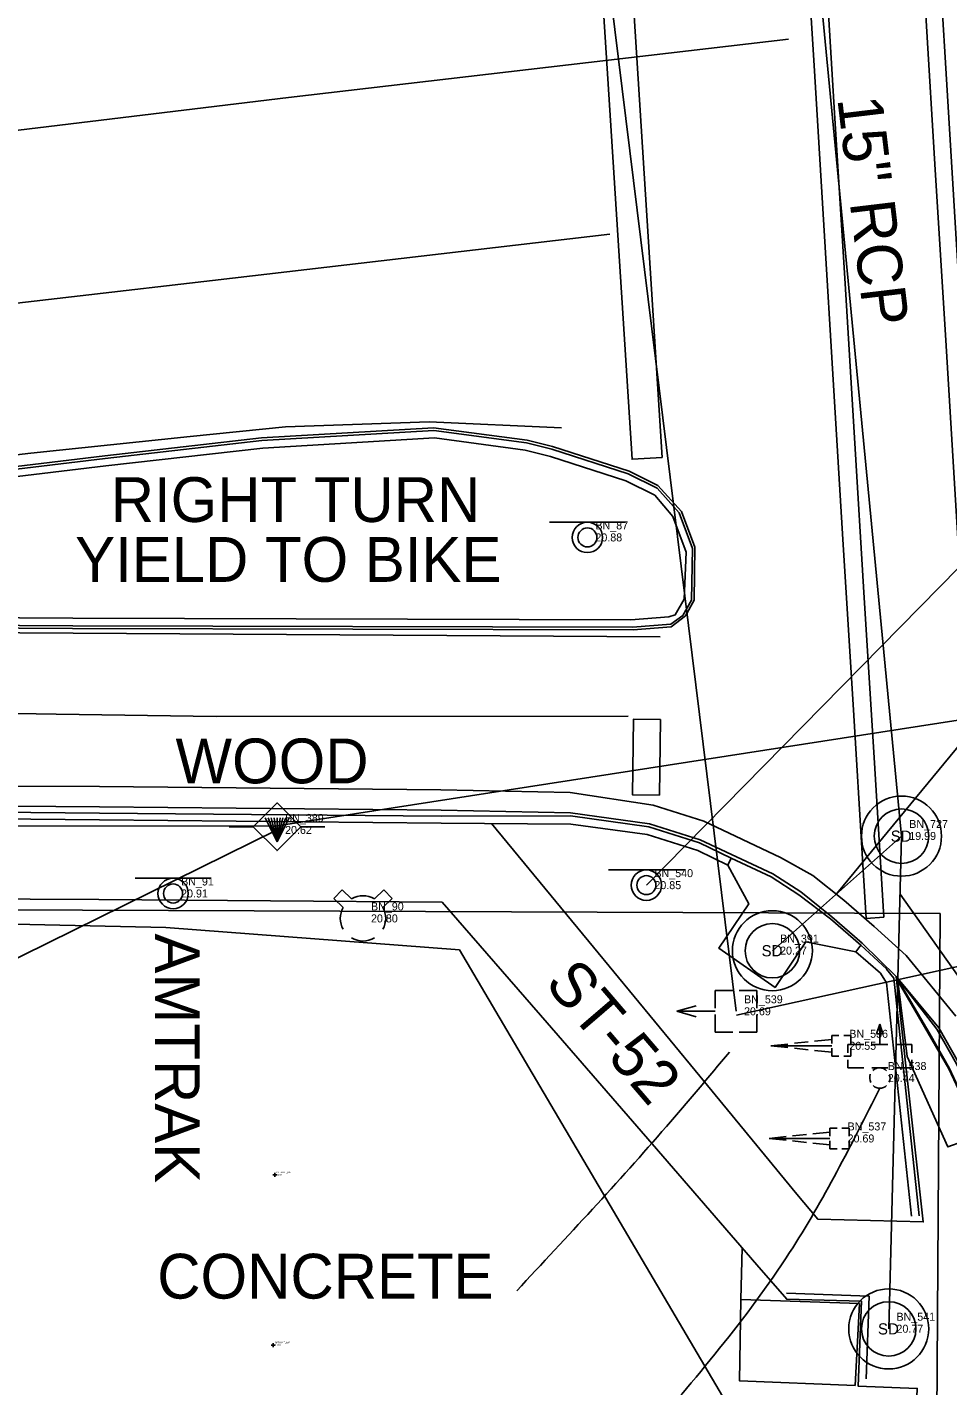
# Model space of a CAD drawing. Extents: x 509744 to 512285, y 1314862 to 1316822.
# Drawn here: x 510403.6 to 510461.1, y 1315900.5 to 1315985.3 of the extents above; entities that cross this region are included whole.
import ezdxf

# ---------------------------------------------------------------- set-up
doc = ezdxf.new("R2010")
doc.units = 0
for name, color, linetype in [('CGBack_ep', 7, 'Continuous'), ('CGep_ep', 7, 'Continuous'), ('CGFace_ep', 7, 'Continuous'), ('ConcSlabs_ep', 7, 'Continuous'), ('CurbRampWarning_ep', 7, 'Continuous'), ('ElecAer_ep', 7, 'Continuous'), ('Fence_ep', 7, 'Continuous'), ('FireHydrant_ep', 7, 'Continuous'), ('GroundShot_ep', 7, 'Continuous'), ('InletCurb_ep', 7, 'Continuous'), ('LaneLine_ep', 7, 'Continuous'), ('ManholeSW_ep', 7, 'Continuous'), ('NonPlottingEle_dp', 7, 'Continuous'), ('PavtAsphalt_ep', 7, 'Continuous'), ('PavtAsphaltCrown_ep', 7, 'Continuous'), ('PedSignal_ep', 7, 'Continuous'), ('PipeCulvert_ep', 7, 'Continuous'), ('PMRK_ep', 7, 'Continuous'), ('PoleElecT_ep', 7, 'Continuous'), ('Railing_ep', 7, 'Continuous'), ('RailroadSgnalG_ep', 7, 'Continuous'), ('RWLine_ep', 7, 'Continuous'), ('SidewalkBack_ep', 7, 'Continuous'), ('SidewalkFront_ep', 7, 'Continuous'), ('SignSingle_ep', 7, 'Continuous'), ('SpanWireP_ep', 7, 'Continuous'), ('TextElevLabel', 7, 'Continuous'), ('TextPtLabel', 7, 'Continuous'), ('TextTopoLabel_ep', 7, 'Continuous'), ('TextUtilLabel_ep', 7, 'Continuous')]:
    doc.layers.add(name, color=color, linetype=linetype)

msp = doc.modelspace()

# ---------------------------------------------------------------- linework, layer by layer
at = {"layer": 'CGBack_ep'}
msp.add_line((510459.985, 1315922.45), (510457.878, 1315926.019), dxfattribs=at)
for points in [[(510378.725, 1315954.337), (510408.51, 1315957.918), (510418.307, 1315959.038), (510429.051, 1315959.668), (510434.713, 1315958.904), (510436.291, 1315958.502), (510440.994, 1315956.993), (510442.799, 1315956.093), (510443.932, 1315954.758), (510444.764, 1315952.527), (510444.643, 1315949.588), (510444.086, 1315948.624), (510443.69, 1315948.495), (510441.301, 1315948.298), (510406.437, 1315948.404), (510376.439, 1315948.593)], [(510213.46, 1315928.408), (510229.375, 1315930.296), (510243.248, 1315931.974), (510273.032, 1315935.568), (510276.125, 1315936.03), (510276.377, 1315936.024), (510280.928, 1315936.714), (510302.088, 1315936.541), (510332.088, 1315936.326), (510348.105, 1315936.285), (510378.103, 1315936.112), (510408.101, 1315935.812), (510429.466, 1315935.61), (510437.551, 1315935.543), (510442.333, 1315934.901), (510445.496, 1315933.9), (510447.372, 1315932.973)], [(510455.375, 1315927.558), (510456.902, 1315926.228)], [(510458.849, 1315911.063), (510457.292, 1315925.633), (510456.902, 1315926.228)], [(510459.985, 1315922.45), (510461.227, 1315920.273), (510462.296, 1315917.956), (510463.071, 1315916.113), (510463.634, 1315913.677), (510463.9, 1315912.426), (510464.537, 1315902.784)]]:
    msp.add_lwpolyline(points, dxfattribs=at)
at = {"layer": 'CGep_ep'}
for p, q in [((510450.173, 1315932.43), (510451.933, 1315931.309)), ((510457.878, 1315926.019), (510460.548, 1315922.827))]:
    msp.add_line(p, q, dxfattribs=at)
for points in [[(510276.079, 1315936.399), (510280.835, 1315937.233), (510302.092, 1315937.104), (510332.093, 1315937.07), (510348.11, 1315937.028), (510378.109, 1315936.856), (510408.108, 1315936.62), (510429.457, 1315936.417), (510437.543, 1315936.24), (510442.471, 1315935.569), (510445.634, 1315934.569), (510450.173, 1315932.43)], [(510451.933, 1315931.309), (510453.878, 1315929.746), (510455.769, 1315928.109), (510457.878, 1315926.019)], [(510460.548, 1315922.827), (510461.79, 1315920.65), (510462.859, 1315918.334), (510463.728, 1315916.277), (510464.291, 1315913.842), (510464.558, 1315912.591), (510465.152, 1315902.835), (510465.225, 1315900.335), (510465.247, 1315897.83), (510465.299, 1315897.273)]]:
    msp.add_lwpolyline(points, dxfattribs=at)
at = {"layer": 'CGFace_ep'}
msp.add_line((510460.425, 1315922.745), (510457.878, 1315926.019), dxfattribs=at)
for points in [[(510378.675, 1315954.8), (510408.461, 1315958.382), (510418.257, 1315959.501), (510429.001, 1315960.131), (510434.797, 1315959.362), (510436.376, 1315958.961), (510441.146, 1315957.434), (510442.951, 1315956.534), (510444.337, 1315954.988), (510445.169, 1315952.758), (510445.107, 1315949.544), (510444.55, 1315948.58), (510443.799, 1315948.042), (510441.411, 1315947.844), (510406.435, 1315947.938), (510376.437, 1315948.126)], [(510213.423, 1315928.708), (510229.342, 1315930.595), (510243.211, 1315932.274), (510272.992, 1315935.887), (510276.086, 1315936.348), (510276.338, 1315936.343), (510280.865, 1315937.071), (510302.091, 1315936.935), (510332.09, 1315936.735), (510348.107, 1315936.694), (510378.107, 1315936.522), (510408.105, 1315936.235), (510429.461, 1315936.033), (510437.545, 1315936.052), (510442.43, 1315935.372), (510445.594, 1315934.372), (510447.588, 1315933.427)], [(510455.683, 1315927.989), (510457.294, 1315926.481)], [(510457.29, 1315926.485), (510457.737, 1315925.926), (510459.314, 1315911.085)], [(510460.425, 1315922.745), (510461.667, 1315920.568), (510462.736, 1315918.251), (510463.585, 1315916.241), (510464.148, 1315913.806), (510464.414, 1315912.555), (510465.07, 1315902.828), (510465.124, 1315900.326), (510465.146, 1315897.822), (510465.191, 1315897.26)]]:
    msp.add_lwpolyline(points, dxfattribs=at)
at = {"layer": 'ConcSlabs_ep'}
for points in [[(510448.259, 1315909.084), (510448.188, 1315905.844), (510448.104, 1315900.766), (510455.334, 1315900.479)], [(510448.188, 1315905.844), (510455.596, 1315905.592), (510455.334, 1315900.479)]]:
    msp.add_lwpolyline(points, dxfattribs=at)
at = {"layer": 'CurbRampWarning_ep'}
msp.add_lwpolyline([(510458.571, 1315921.024), (510461.121, 1315915.38), (510462.986, 1315916.049), (510462.268, 1315917.937), (510461.17, 1315920.249), (510457.981, 1315925.75), (510458.571, 1315921.024)], dxfattribs=at)
at = {"layer": 'ElecAer_ep'}
msp.add_line((510350.63, 1315901.414), (510419.206, 1315935.18), dxfattribs=at)
for points in [[(510447.916, 1315923.604), (510519.717, 1315939.401), (510434.348, 1316033.385), (510447.882, 1315923.851)], [(510525.108, 1315951.865), (510419.206, 1315935.43), (510273.562, 1315935.372), (510178.5, 1315925.306)]]:
    msp.add_lwpolyline(points, dxfattribs=at)
at = {"layer": 'Fence_ep'}
msp.add_lwpolyline([(510352.686, 1315930.397), (510412.246, 1315929.078), (510430.594, 1315927.685), (510450.269, 1315894.332), (510413.623, 1315877.394)], dxfattribs=at)
at = {"layer": 'FireHydrant_ep'}
for p, q in [((510422.746, 1315930.9), (510423.271, 1315931.437)), ((510422.746, 1315930.9), (510423.331, 1315930.335)), ((510423.271, 1315931.437), (510423.854, 1315930.875)), ((510425.874, 1315931.435), (510425.294, 1315930.875)), ((510426.4, 1315930.897), (510425.817, 1315930.335)), ((510426.4, 1315930.897), (510425.874, 1315931.435))]:
    msp.add_line(p, q, dxfattribs=at)
for start, end in [(59.47352, 120.52648), (151.26736, 208.73264), (331.26736, 28.73264), (239.47352, 300.52648)]:
    msp.add_arc((510424.574, 1315929.654), 1.417, start, end, dxfattribs=at)
at = {"layer": 'GroundShot_ep'}
for p, q in [((510419.182, 1315913.643), (510418.932, 1315913.643)), ((510419.057, 1315913.518), (510419.057, 1315913.768)), ((510419.095, 1315903.006), (510418.845, 1315903.006)), ((510418.97, 1315902.881), (510418.97, 1315903.131))]:
    msp.add_line(p, q, dxfattribs=at)
at = {"layer": 'InletCurb_ep'}
msp.add_lwpolyline([(510447.588, 1315933.427), (510447.372, 1315932.973), (510448.681, 1315930.574), (510446.802, 1315927.803), (510450.323, 1315925.348), (510452.243, 1315928.185), (510455.375, 1315927.558), (510455.683, 1315927.989), (510453.792, 1315929.627), (510451.809, 1315931.137), (510450.084, 1315932.245)], close=True, dxfattribs=at)
at = {"layer": 'LaneLine_ep'}
msp.add_lwpolyline([(510415.397, 1315942.269), (510405.399, 1315942.422), (510395.4, 1315942.575), (510391.37, 1315942.637), (510381.371, 1315942.674), (510371.371, 1315942.711), (510361.371, 1315942.749), (510351.371, 1315942.786), (510341.371, 1315942.823), (510331.372, 1315942.86), (510321.372, 1315942.898), (510311.372, 1315942.935), (510301.372, 1315942.972), (510291.372, 1315943.01), (510281.373, 1315943.047), (510271.373, 1315943.084), (510270.393, 1315943.088), (510260.461, 1315941.925), (510250.529, 1315940.763), (510240.596, 1315939.6), (510230.664, 1315938.438), (510220.732, 1315937.276), (510210.8, 1315936.113), (510209.026, 1315935.906)], dxfattribs=at)
at = {"layer": 'ManholeSW_ep'}
for centre, radius in [((510458.221, 1315934.794), 2.5), ((510458.221, 1315934.794), 1.7), ((510450.152, 1315927.634), 2.5), ((510450.152, 1315927.634), 1.7), ((510457.421, 1315904.013), 2.5), ((510457.421, 1315904.013), 1.7)]:
    msp.add_circle(centre, radius, dxfattribs=at)
at = {"layer": 'NonPlottingEle_dp'}
for p, q in [((510454.186, 1315931.214), (510469.622, 1315949.938)), ((510458.127, 1315931.159), (510468.417, 1315916.642))]:
    msp.add_line(p, q, dxfattribs=at)
at = {"layer": 'PavtAsphalt_ep'}
for p, q in [((510450.666, 1315933.454), (510452.673, 1315932.343)), ((510458.517, 1315927.345), (510461.616, 1315923.543))]:
    msp.add_line(p, q, dxfattribs=at)
for points in [[(510378.658, 1315954.967), (510408.443, 1315958.548), (510418.239, 1315959.668), (510428.983, 1315960.298), (510434.828, 1315959.526), (510436.406, 1315959.125), (510441.2, 1315957.592), (510443.006, 1315956.692), (510444.482, 1315955.071), (510445.315, 1315952.841), (510445.273, 1315949.529), (510444.717, 1315948.565), (510443.838, 1315947.879), (510441.45, 1315947.682), (510406.434, 1315947.771), (510376.436, 1315947.959)], [(510213.416, 1315928.765), (510243.204, 1315932.332), (510272.986, 1315935.937), (510276.079, 1315936.399), (510276.158, 1315937.804), (510280.621, 1315938.433), (510302.101, 1315938.323), (510332.1, 1315938.147), (510348.117, 1315938.106), (510378.119, 1315937.934), (510408.119, 1315937.895), (510429.442, 1315937.693), (510437.528, 1315937.516), (510442.712, 1315936.736), (510445.876, 1315935.736), (510450.666, 1315933.454)], [(510452.673, 1315932.343), (510454.626, 1315930.792), (510456.518, 1315929.155), (510458.517, 1315927.345)]]:
    msp.add_lwpolyline(points, dxfattribs=at)
at = {"layer": 'PavtAsphaltCrown_ep'}
msp.add_lwpolyline([(510320.657, 1315968.893), (510345.475, 1315971.905), (510370.293, 1315974.916), (510395.111, 1315977.927), (510419.929, 1315980.938), (510451.151, 1315984.577)], dxfattribs=at)
at = {"layer": 'PedSignal_ep'}
for p, q in [((510456.858, 1315923.044), (510456.66, 1315922.444)), ((510456.66, 1315922.444), (510457.056, 1315922.444)), ((510456.858, 1315921.769), (510456.858, 1315923.044)), ((510456.858, 1315923.044), (510457.056, 1315922.444)), ((510454.858, 1315921.769), (510455.858, 1315921.769)), ((510454.858, 1315921.769), (510454.858, 1315921.262)), ((510456.358, 1315921.769), (510457.358, 1315921.769)), ((510457.858, 1315921.769), (510458.858, 1315921.769)), ((510458.858, 1315921.769), (510458.858, 1315921.262)), ((510454.858, 1315920.827), (510454.858, 1315920.319)), ((510458.858, 1315920.827), (510458.858, 1315920.319)), ((510454.858, 1315920.319), (510455.858, 1315920.319)), ((510456.358, 1315920.319), (510457.358, 1315920.319)), ((510457.858, 1315920.319), (510458.858, 1315920.319))]:
    msp.add_line(p, q, dxfattribs=at)
for centre, radius, start, end in [((510457.001, 1315919.702), 0.766, 163.88316, 202.84976), ((510456.85, 1315919.703), 0.616, 45.06774, 132.92209), ((510457.076, 1315919.659), 0.437, 329.03624, 30.96376), ((510456.866, 1315919.661), 0.617, 227.10453, 312.89547)]:
    msp.add_arc(centre, radius, start, end, dxfattribs=at)
at = {"layer": 'PipeCulvert_ep'}
msp.add_line((510457.421, 1315904.013), (510458.221, 1315934.794), dxfattribs=at)
for points in [[(510453.061, 1315988.58), (510458.221, 1315934.794)], [(510458.221, 1315934.794), (510450.152, 1315927.634)]]:
    msp.add_lwpolyline(points, dxfattribs=at)
at = {"layer": 'PMRK_ep'}
msp.add_line((510441.149, 1315942.289), (510415.397, 1315942.269), dxfattribs=at)
for points in [[(510452.145, 1315992.914), (510452.755, 1315982.932), (510453.365, 1315972.951), (510453.975, 1315962.97), (510454.586, 1315952.988), (510455.196, 1315943.007), (510455.806, 1315933.026), (510456.012, 1315929.656), (510457.115, 1315929.724)], [(510457.115, 1315929.724), (510456.505, 1315939.705), (510455.895, 1315949.686), (510455.285, 1315959.668), (510454.675, 1315969.649), (510454.065, 1315979.631), (510453.454, 1315989.612)], [(510460.575, 1315989.648), (510461.183, 1315979.666), (510461.792, 1315969.685), (510462.4, 1315959.703), (510463.008, 1315949.722), (510463.616, 1315939.74), (510464.225, 1315929.759), (510464.439, 1315926.245), (510463.393, 1315926.182), (510462.785, 1315936.163), (510462.177, 1315946.145), (510461.568, 1315956.126), (510460.96, 1315966.108), (510460.352, 1315976.089), (510459.744, 1315986.071)], [(510440.007, 1315972.392), (510415.174, 1315969.509), (510390.341, 1315966.626), (510372.351, 1315964.538)], [(510244.508, 1315949.203), (510254.435, 1315950.402), (510264.363, 1315951.601), (510269.019, 1315952.164), (510279.018, 1315952.146), (510289.018, 1315952.128), (510299.018, 1315952.11), (510309.018, 1315952.092), (510319.018, 1315952.074), (510329.018, 1315952.056), (510339.018, 1315952.038), (510341.783, 1315952.033), (510351.648, 1315952.575), (510361.58, 1315953.744), (510371.511, 1315954.912), (510381.443, 1315956.081), (510391.374, 1315957.25), (510401.306, 1315958.419), (510403.828, 1315958.716), (510413.773, 1315959.749), (510419.735, 1315960.369), (510428.704, 1315960.675), (510436.969, 1315960.307)], [(510443.135, 1315947.24), (510433.135, 1315947.305), (510423.136, 1315947.37), (510413.136, 1315947.435), (510403.136, 1315947.5), (510393.137, 1315947.565), (510383.137, 1315947.63), (510373.138, 1315947.695), (510363.138, 1315947.76), (510353.138, 1315947.825), (510343.139, 1315947.89), (510333.139, 1315947.955), (510323.14, 1315948.021), (510313.14, 1315948.086), (510312.499, 1315948.09), (510302.499, 1315948.076), (510292.499, 1315948.061), (510282.499, 1315948.047), (510272.499, 1315948.033), (510269.518, 1315948.029), (510259.574, 1315946.968), (510249.631, 1315945.907), (510247.552, 1315945.685), (510237.627, 1315944.463)]]:
    msp.add_lwpolyline(points, dxfattribs=at)
for points in [[(510441.092, 1315992.647), (510443.264, 1315958.455), (510441.387, 1315958.336), (510439.215, 1315992.528)], [(510443.159, 1315942.081), (510443.09, 1315937.354), (510441.407, 1315937.378), (510441.476, 1315942.105)]]:
    msp.add_lwpolyline(points, close=True, dxfattribs=at)
at = {"layer": 'PoleElecT_ep'}
for p, q in [((510416.219, 1315935.38), (510417.719, 1315935.38)), ((510419.206, 1315934.433), (510418.459, 1315935.927)), ((510419.206, 1315934.433), (510418.654, 1315935.927)), ((510419.206, 1315934.433), (510418.83, 1315935.927)), ((510419.206, 1315934.433), (510419.024, 1315935.927)), ((510419.206, 1315934.433), (510419.953, 1315935.927)), ((510419.206, 1315934.433), (510419.571, 1315935.927)), ((510419.206, 1315934.433), (510419.747, 1315935.927)), ((510419.206, 1315934.433), (510419.389, 1315935.927)), ((510419.206, 1315934.433), (510419.206, 1315935.927)), ((510422.194, 1315935.38), (510420.694, 1315935.38))]:
    msp.add_line(p, q, dxfattribs=at)
msp.add_lwpolyline([(510417.719, 1315935.38), (510419.206, 1315936.868), (510420.694, 1315935.38), (510419.206, 1315933.892), (510417.719, 1315935.38)], dxfattribs=at)
at = {"layer": 'Railing_ep'}
msp.add_lwpolyline([(510451.029, 1315906.249), (510456.198, 1315906.057), (510456.007, 1315900.887)], dxfattribs=at)
at = {"layer": 'RailroadSgnalG_ep'}
for p, q in [((510450.06, 1315921.697), (510451.128, 1315921.809)), ((510450.06, 1315921.697), (510451.128, 1315921.584)), ((510450.06, 1315921.697), (510453.86, 1315921.697)), ((510451.526, 1315921.851), (510452.395, 1315921.942)), ((510451.526, 1315921.542), (510452.395, 1315921.451)), ((510452.793, 1315921.984), (510453.86, 1315922.097)), ((510453.86, 1315921.843), (510453.86, 1315922.347)), ((510453.86, 1315922.347), (510454.31, 1315922.347)), ((510453.86, 1315921.047), (510453.86, 1315921.543)), ((510455.06, 1315922.347), (510454.61, 1315922.347)), ((510455.06, 1315922.347), (510455.06, 1315921.843)), ((510455.06, 1315921.047), (510455.06, 1315921.543)), ((510452.793, 1315921.409), (510453.86, 1315921.297)), ((510453.86, 1315921.047), (510454.31, 1315921.047)), ((510454.61, 1315921.047), (510455.06, 1315921.047)), ((510453.751, 1315916.055), (510453.751, 1315916.559)), ((510453.751, 1315916.559), (510454.201, 1315916.559)), ((510454.951, 1315916.559), (510454.501, 1315916.559)), ((510454.951, 1315916.559), (510454.951, 1315916.055)), ((510449.951, 1315915.909), (510451.019, 1315916.021)), ((510449.951, 1315915.909), (510451.019, 1315915.797)), ((510449.951, 1315915.909), (510453.751, 1315915.909)), ((510451.417, 1315916.063), (510452.286, 1315916.155)), ((510451.417, 1315915.755), (510452.286, 1315915.663)), ((510452.684, 1315916.197), (510453.751, 1315916.309)), ((510452.684, 1315915.621), (510453.751, 1315915.509)), ((510453.751, 1315915.259), (510453.751, 1315915.755)), ((510454.951, 1315915.259), (510454.951, 1315915.755)), ((510453.751, 1315915.259), (510454.201, 1315915.259)), ((510454.501, 1315915.259), (510454.951, 1315915.259))]:
    msp.add_line(p, q, dxfattribs=at)
at = {"layer": 'RWLine_ep'}
for p in [(510318.071, 1315930.486), (510460.422, 1315897.456)]:
    msp.add_line(p, (510460.629, 1315929.965), dxfattribs=at)
at = {"layer": 'SidewalkBack_ep'}
for points in [[(510214.596, 1315919.181), (510230.395, 1315921.045), (510244.394, 1315922.662), (510274.213, 1315925.965), (510275.638, 1315926.243), (510275.771, 1315926.761), (510277.251, 1315926.882), (510277.499, 1315926.905), (510282.582, 1315927.469), (510302.041, 1315929.664), (510332.047, 1315930.441), (510348.067, 1315930.806), (510378.059, 1315930.978), (510408.059, 1315930.844), (510429.523, 1315930.674)], [(510429.523, 1315930.674), (510436.078, 1315923.121), (510442.632, 1315915.569), (510449.186, 1315908.016), (510451.055, 1315905.862), (510455.724, 1315905.741), (510455.517, 1315900.434), (510459.2, 1315900.29), (510458.953, 1315893.996)]]:
    msp.add_lwpolyline(points, dxfattribs=at)
at = {"layer": 'SidewalkFront_ep'}
msp.add_lwpolyline([(510432.608, 1315935.584), (510438.969, 1315927.868), (510445.33, 1315920.151), (510451.691, 1315912.435), (510452.983, 1315910.867), (510459.58, 1315910.7), (510458.478, 1315920.625), (510457.878, 1315926.019)], dxfattribs=at)
at = {"layer": 'SignSingle_ep'}
for p, q in [((510436.22, 1315954.404), (510440.97, 1315954.404)), ((510439.905, 1315932.682), (510444.655, 1315932.682)), ((510410.334, 1315932.161), (510415.084, 1315932.161))]:
    msp.add_line(p, q, dxfattribs=at)
for centre, radius in [((510438.595, 1315953.454), 0.95), ((510438.595, 1315953.454), 0.594), ((510442.28, 1315931.732), 0.95), ((510412.709, 1315931.211), 0.95), ((510412.709, 1315931.211), 0.594), ((510442.28, 1315931.732), 0.594)]:
    msp.add_circle(centre, radius, dxfattribs=at)
at = {"layer": 'SpanWireP_ep'}
for p, q in [((510446.582, 1315924.051), (510446.582, 1315925.151)), ((510446.582, 1315925.151), (510447.682, 1315925.151)), ((510448.082, 1315925.151), (510449.182, 1315925.151)), ((510449.182, 1315924.051), (510449.182, 1315925.151)), ((510444.182, 1315923.851), (510445.382, 1315924.201)), ((510444.182, 1315923.851), (510446.582, 1315923.851)), ((510444.182, 1315923.851), (510445.382, 1315923.501)), ((510446.582, 1315922.551), (510446.582, 1315923.651)), ((510449.182, 1315922.551), (510449.182, 1315923.651)), ((510446.582, 1315922.551), (510447.682, 1315922.551)), ((510448.082, 1315922.551), (510449.182, 1315922.551))]:
    msp.add_line(p, q, dxfattribs=at)
at = {"layer": 'TextTopoLabel_ep'}
msp.add_line((510442.28, 1315931.732), (510465.537, 1315955.388), dxfattribs=at)
msp.add_spline([(510442.065, 1315897.1), (510451.227, 1315908.777), (510456.866, 1315919.044)], degree=3, dxfattribs=at)
at = {"layer": 'TextUtilLabel_ep'}
msp.add_spline([(510434.176, 1315906.395), (510443.54, 1315916.663), (510447.466, 1315921.293)], degree=3, dxfattribs=at)

# ---------------------------------------------------------------- texts
at = {"layer": 'ManholeSW_ep'}
for p in [(510457.548, 1315934.444), (510449.479, 1315927.284), (510456.749, 1315903.663)]:
    msp.add_text('SD', height=0.7, dxfattribs=at).set_placement(p)
at = {"layer": 'NonPlottingEle_dp'}
for s, rotation, p in [('15" RCP', 276.83085, (510454.208, 1315980.867)), ('ST-52', 310.62151, (510435.863, 1315925.553))]:
    msp.add_text(s, height=2.8, rotation=rotation, dxfattribs=at).set_placement(p)
at = {"layer": 'TextElevLabel'}
for s, height, p in [('20.88', 0.5, (510439.095, 1315953.204)), ('20.62', 0.5, (510419.706, 1315934.93)), ('19.99', 0.5, (510458.705, 1315934.554)), ('20.85', 0.5, (510442.78, 1315931.482)), ('20.91', 0.5, (510413.209, 1315930.961)), ('20.80', 0.5, (510425.074, 1315929.404)), ('20.27', 0.5, (510450.635, 1315927.394)), ('20.69', 0.5, (510448.382, 1315923.601)), ('20.55', 0.5, (510454.96, 1315921.447)), ('20.44', 0.5, (510457.363, 1315919.432)), ('20.69', 0.5, (510454.851, 1315915.659)), ('21.06', 0.1, (510419.157, 1315913.593)), ('20.77', 0.5, (510457.905, 1315903.773)), ('20.88', 0.1, (510419.07, 1315902.956))]:
    msp.add_text(s, height=height, dxfattribs=at).set_placement(p)
at = {"layer": 'TextPtLabel'}
for s, height, p in [('BN_87', 0.5, (510439.095, 1315953.954)), ('BN_389', 0.5, (510419.706, 1315935.68)), ('BN_727', 0.5, (510458.705, 1315935.304)), ('BN_540', 0.5, (510442.78, 1315932.232)), ('BN_91', 0.5, (510413.209, 1315931.711)), ('BN_90', 0.5, (510425.074, 1315930.154)), ('BN_391', 0.5, (510450.635, 1315928.144)), ('BN_539', 0.5, (510448.382, 1315924.351)), ('BN_536', 0.5, (510454.96, 1315922.197)), ('BN_538', 0.5, (510457.363, 1315920.182)), ('BN_537', 0.5, (510454.851, 1315916.409)), ('DEFAULT_667', 0.1, (510419.157, 1315913.743)), ('BN_541', 0.5, (510457.905, 1315904.523)), ('DEFAULT_668', 0.1, (510419.07, 1315903.106))]:
    msp.add_text(s, height=height, dxfattribs=at).set_placement(p)
at = {"layer": 'TextTopoLabel_ep'}
for s, p in [('RIGHT TURN', (510408.815, 1315954.417)), ('YIELD TO BIKE', (510406.589, 1315950.678)), ('WOOD', (510412.859, 1315938.092)), ('CONCRETE', (510411.72, 1315905.904))]:
    msp.add_text(s, height=2.8, dxfattribs=at).set_placement(p)
msp.add_text('AMTRAK', height=2.8, rotation=270, dxfattribs=at).set_placement((510411.571, 1315928.715))

doc.saveas('drawing.dxf')
